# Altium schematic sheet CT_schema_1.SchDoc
size 385 x 258 mm
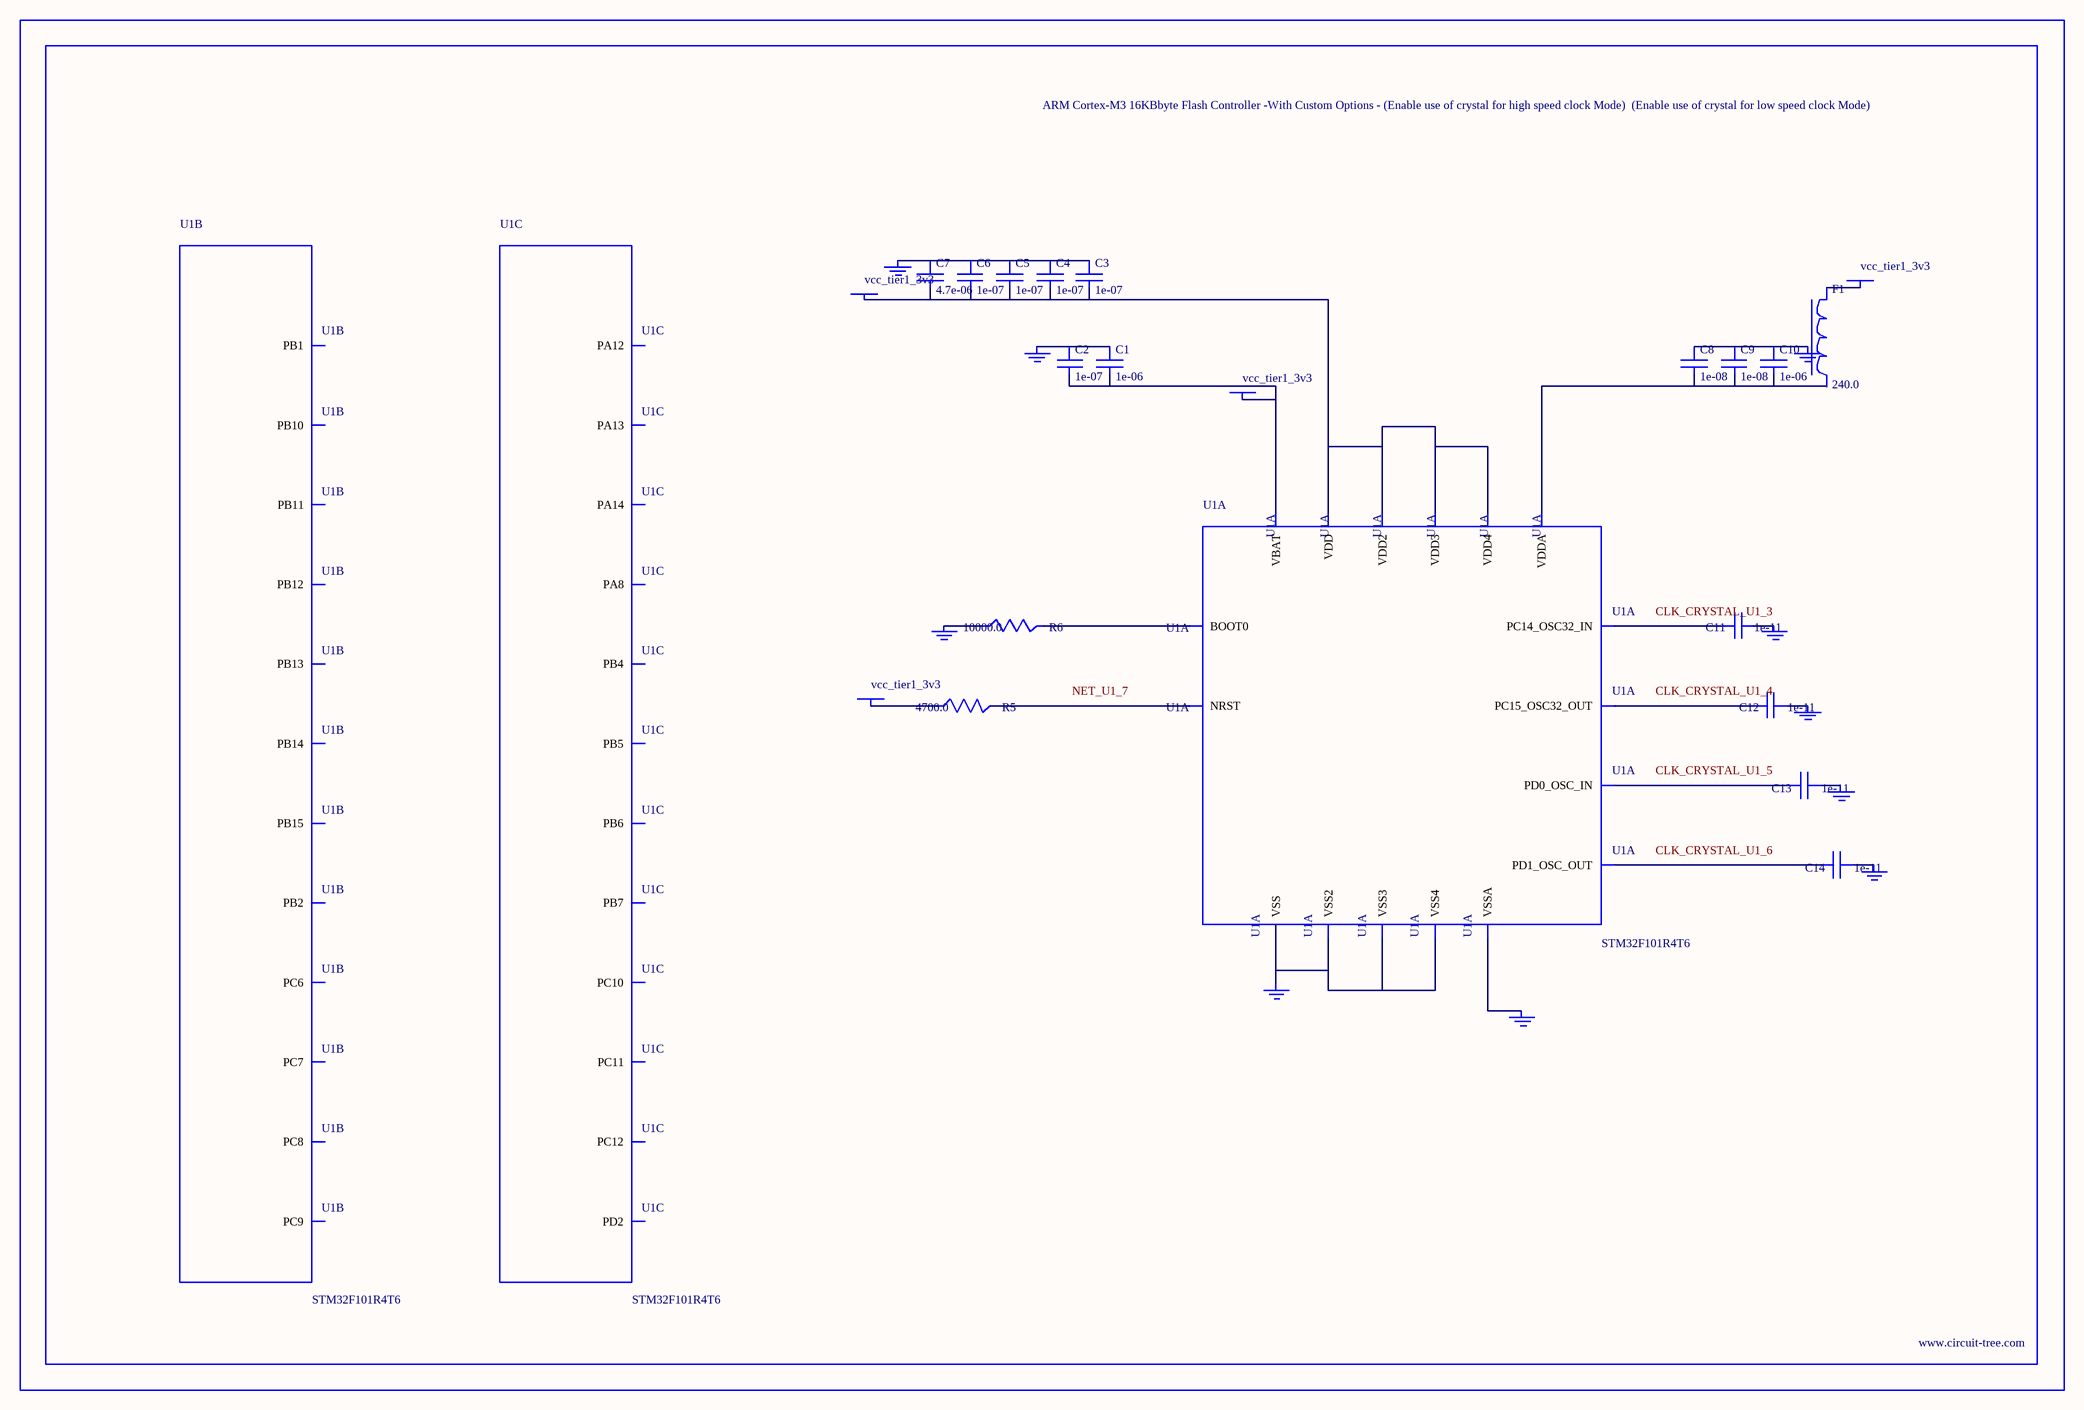
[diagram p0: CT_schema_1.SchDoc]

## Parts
BORDER0  (no value)
C1  1e-06  [C0603]
C2  1e-07  [C0603]
C3  1e-07  [C0603]
C4  1e-07  [C0603]
C5  1e-07  [C0603]
C6  1e-07  [C0603]
C7  4.7e-06  [C0603]
C8  1e-08  [C0603]
C9  1e-08  [C0603]
C10  1e-06  [C0603]
C11  1e-11  [C0402]
C12  1e-11  [C0402]
C13  1e-11  [C0402]
C14  1e-11  [C0402]
F1  240.0  [L0603]
GND_INSTANCE_0_0  (no value)
GND_INSTANCE_0_1  (no value)
GND_INSTANCE_0_2  (no value)
GND_INSTANCE_0_3  (no value)
GND_INSTANCE_0_4  (no value)
GND_INSTANCE_0_5  (no value)
GND_INSTANCE_0_6  (no value)
GND_INSTANCE_0_7  (no value)
GND_INSTANCE_0_8  (no value)
GND_INSTANCE_0_9  (no value)
POWER_INSTANCE_0_0  vcc_tier1_3v3
POWER_INSTANCE_0_1  vcc_tier1_3v3
POWER_INSTANCE_0_2  vcc_tier1_3v3
POWER_INSTANCE_0_3  vcc_tier1_3v3
R5  4700.0  [R0603]
R6  10000.0  [R0603]
U1  STM32F101R4T6  [LQFP64]  (parts A,B,C of 7)

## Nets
NetC1_1: C1.1 C2.1 GND_INSTANCE_0_0.0(GND)
NetC1_2: C1.2 C2.2 POWER_INSTANCE_0_0.0(PWR) U1.1(VBAT)
NetC3_1: C3.1 C4.1 C5.1 C6.1 C7.1 GND_INSTANCE_0_7.0(GND)
NetC3_2: C3.2 C4.2 C5.2 C6.2 C7.2 POWER_INSTANCE_0_2.0(PWR) U1.19(VDD) U1.32(VDD2) U1.48(VDD3) U1.64(VDD4)
NetC8_1: C8.1 C9.1 C10.1 GND_INSTANCE_0_6.0(GND)
NetC8_2: C8.2 C9.2 C10.2 U1.13(VDDA)
NetC11_1: C11.1 GND_INSTANCE_0_1.0(GND)
NetC11_2: C11.2 U1.3(PC14_OSC32_IN)
NetC12_1: C12.1 GND_INSTANCE_0_2.0(GND)
NetC12_2: C12.2 U1.4(PC15_OSC32_OUT)
NetC13_1: C13.1 GND_INSTANCE_0_3.0(GND)
NetC13_2: C13.2 U1.5(PD0_OSC_IN)
NetC14_1: C14.1 GND_INSTANCE_0_4.0(GND)
NetC14_2: C14.2 U1.6(PD1_OSC_OUT)
NetF1_1: F1.1 POWER_INSTANCE_0_1.0(PWR)
NetGND_INSTANCE_0_5_0: GND_INSTANCE_0_5.0(GND) U1.12(VSSA)
NetGND_INSTANCE_0_8_0: GND_INSTANCE_0_8.0(GND) R6.1
NetGND_INSTANCE_0_9_0: GND_INSTANCE_0_9.0(GND) U1.18(VSS) U1.31(VSS2) U1.47(VSS3) U1.63(VSS4)
NetPOWER_INSTANCE_0_3_0: POWER_INSTANCE_0_3.0(PWR) R5.1
NetR5_2: R5.2 U1.7(NRST)
NetR6_2: R6.2 U1.60(BOOT0)

Not connected (* = marked no-connect by the designer): F1 2; U1 27(PB1) 28(PB2) 29(PB10) 30(PB11) 33(PB12) 34(PB13) 35(PB14) 36(PB15) 37(PC6) 38(PC7) 39(PC8) 40(PC9) 41(PA8) 45(PA12) 46(PA13) 49(PA14) 51(PC10) 52(PC11) 53(PC12) 54(PD2) 56(PB4) 57(PB5) 58(PB6) 59(PB7)

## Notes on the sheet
- Labels drawn without touching a wire or pin: CLK_CRYSTAL_U1_3, CLK_CRYSTAL_U1_4, CLK_CRYSTAL_U1_5, CLK_CRYSTAL_U1_6, NET_U1_7

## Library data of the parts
BORDER0 = BORDER_PAGE0
C1 C10 = C0603C105K3RACTU
C2-C6 = 06035C104K4Z2A
C7 = GRM188R6YA475KE15D
C8 C9 = 06035C103K4Z2A
C11-C14 = C0402C100K3GACTU
F1 = Z0603C241ASMST
GND_INSTANCE_0_0-GND_INSTANCE_0_9 = GND
POWER_INSTANCE_0_0-POWER_INSTANCE_0_3 = PWR
R5 = RC0603JR-074K7L
R6 = RC0603JR-0710KL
